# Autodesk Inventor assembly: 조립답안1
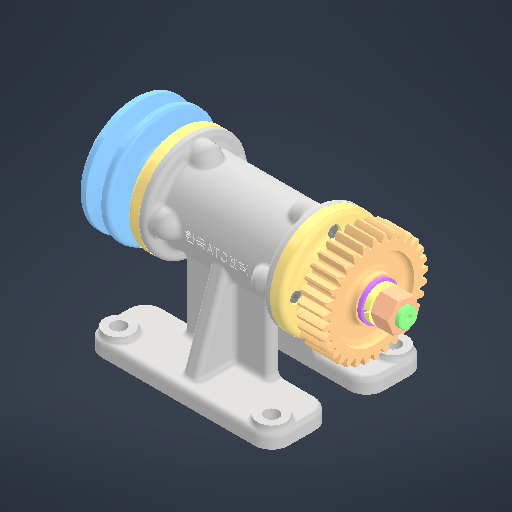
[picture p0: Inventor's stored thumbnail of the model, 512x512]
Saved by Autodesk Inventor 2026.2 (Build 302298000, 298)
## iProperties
Created: 2026-06
Part Number: 조립답안1
Document SubType Name: Assembly
Designer: sec7
Author: sec7
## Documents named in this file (13)
- C:\Users\sec7\Desktop\2026.06.20\760603V1014 (1)\조립답안1.iam
- C:\Users\sec7\Desktop\2026.06.20\본체.ipt
- C:\Users\sec7\Desktop\2026.06.20\깊은 홈 볼 베어링 6904.ipt
- C:\Users\sec7\Desktop\2026.06.20\커버.ipt
- C:\Users\sec7\Desktop\2026.06.20\축.ipt
- C:\Users\sec7\Desktop\2026.06.20\평행 키 4x4x14.ipt
- C:\Users\sec7\Desktop\2026.06.20\오일 실 20 35 8.ipt
- C:\Users\sec7\Desktop\2026.06.20\6각 구멍붙이 볼트 M4x8.ipt
- C:\Users\sec7\Desktop\2026.06.20\스퍼 기어.ipt
- C:\Users\sec7\Desktop\2026.06.20\V 벨트 풀리.ipt
- C:\Users\sec7\Desktop\2026.06.20\평 와셔 M12.ipt
- C:\Users\sec7\Desktop\2026.06.20\스프링 와셔 M12.ipt
- C:\Users\sec7\Desktop\2026.06.20\6각 너트 M12x1.ipt
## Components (11 placed, 3 different names)
1. 6각 구멍붙이 볼트 M4x8:1
2. 6각 구멍붙이 볼트 M4x8:2
3. 6각 구멍붙이 볼트 M4x8:3
4. 6각 구멍붙이 볼트 M4x8:4
5. 6각 구멍붙이 볼트 M4x8:5
6. 6각 구멍붙이 볼트 M4x8:6
7. 6각 구멍붙이 볼트 M4x8:7
8. 6각 구멍붙이 볼트 M4x8:8
9. V 벨트 풀리:1
10. 6각 너트 M12x1:1
11. 6각 너트 M12x1:2
